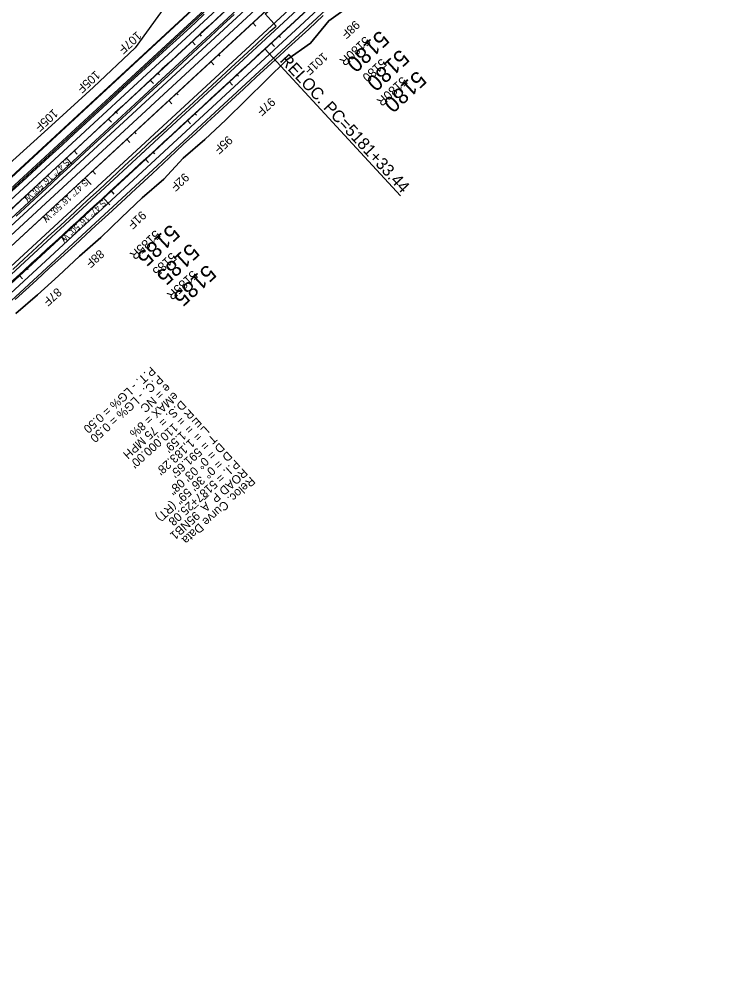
# Model space of a CAD drawing. Extents: x 2160876 to 2175990, y 601436 to 618246.
# Drawn here: x 2171138 to 2172369, y 611423 to 613107 of the extents above; entities that cross this region are included whole.
import ezdxf

# ---------------------------------------------------------------- set-up
doc = ezdxf.new("R2010")
doc.units = 0
for name, color, linetype in [('BNDY-ADJ', 7, 'Continuous'), ('BNDY-ADJ-TXT', 7, 'Continuous'), ('EX-UTIL-ELEC-TXT', 7, 'Continuous'), ('GN_Transparent 80', 7, 'Continuous'), ('RD_DTM_Major2', 7, 'Continuous'), ('RD_EX_BldgApp_Sign', 7, 'Continuous'), ('RD_EX_BldgApp_Steps', 7, 'Continuous'), ('RD_EX_DV_TX_Prop', 7, 'Continuous'), ('RD_EX_Fence_Gate', 7, 'Continuous'), ('RD_EX_Parking_Conc', 7, 'Continuous'), ('RD_EX_RW', 7, 'Continuous'), ('RD_HC_Cl', 7, 'Continuous'), ('RD_HC_Data_Tic', 7, 'Continuous'), ('RD_HC_TX_Sta50', 7, 'Continuous'), ('RD_TX_RoadID', 7, 'Continuous')]:
    doc.layers.add(name, color=color, linetype=linetype)

msp = doc.modelspace()

# ---------------------------------------------------------------- linework, layer by layer
at = {"layer": 'BNDY-ADJ'}
msp.add_line((2172239.9, 613739.9), (2163704.8, 605858.6), dxfattribs=at)
at = {"layer": 'BNDY-ADJ-TXT'}
for p, q in [((2172207.3, 613775.1), (2170395.2, 612101.8)), ((2172272.5, 613704.6), (2170460.3, 612031.3))]:
    msp.add_line(p, q, dxfattribs=at)
at = {"layer": 'EX-UTIL-ELEC-TXT'}
for p, q in [((2172179.3, 613805.5), (2170367.1, 612132.2)), ((2172180, 613804.8), (2170367.8, 612131.4)), ((2172199.2, 613784), (2170387, 612110.6)), ((2172207.3, 613775.1), (2170395.2, 612101.8)), ((2172215.5, 613766.3), (2170403.3, 612093)), ((2172264.3, 613713.4), (2170452.2, 612040.1)), ((2172272.5, 613704.6), (2170460.3, 612031.3)), ((2172261.1, 613677.8), (2170468.4, 612022.5))]:
    msp.add_line(p, q, dxfattribs=at)
at = {"layer": 'GN_Transparent 80'}
for p, q in [((2172189.5, 613794.5), (2170377.3, 612121.1)), ((2172191, 613792.8), (2170378.9, 612119.4))]:
    msp.add_line(p, q, dxfattribs=at)
at = {"layer": 'RD_DTM_Major2'}
for p, q in [((2171547.2, 613100.3), (2171552.7, 613094.4)), ((2171473.8, 613032.4), (2171479.2, 613026.6)), ((2171400.3, 612964.6), (2171405.7, 612958.7)), ((2171326.8, 612896.7), (2171332.2, 612890.9)), ((2171253.4, 612828.9), (2171264.2, 612817.2)), ((2171179.9, 612761.1), (2171185.3, 612755.2))]:
    msp.add_line(p, q, dxfattribs=at)
at = {"layer": 'RD_EX_BldgApp_Sign'}
msp.add_line((2170418.2, 612076.8), (2171614.4, 613181.4), dxfattribs=at)
at = {"layer": 'RD_EX_BldgApp_Steps'}
for p, q in [((2172672.7, 614139.6), (2163700.6, 605854.7)), ((2172327.8, 613755.9), (2171568.5, 613054.8)), ((2171454.4, 613080.2), (2171457.2, 613077.2)), ((2171593.1, 613077.4), (2171595.8, 613074.5)), ((2171487.2, 613044.8), (2171489.9, 613041.9)), ((2171806, 612797.6), (2171568.5, 613054.8)), ((2171381.1, 613012.2), (2171383.8, 613009.3)), ((2171519.6, 613009.6), (2171522.3, 613006.7)), ((2171413.7, 612977), (2171416.4, 612974)), ((2171307.8, 612944.2), (2171310.5, 612941.3)), ((2171446.1, 612941.8), (2171448.8, 612938.9)), ((2171340.2, 612909.1), (2171342.9, 612906.2)), ((2171234.5, 612876.2), (2171239.9, 612870.3)), ((2171372.5, 612874.2), (2171375.2, 612871.2)), ((2171266.8, 612841.3), (2171272.2, 612835.4)), ((2171161.3, 612808), (2171164, 612805.1)), ((2171298.8, 612806.5), (2171304.2, 612800.6)), ((2171193.3, 612773.5), (2171196, 612770.5)), ((2171225.1, 612739), (2171227.8, 612736)), ((2171151.3, 612671.5), (2171154, 612668.5))]:
    msp.add_line(p, q, dxfattribs=at)
for centre, start, end in [((2246150.8, 532330.8), 132.719474, 133.343763), ((2096943.5, 693870), 312.103138, 312.719474)]:
    msp.add_arc(centre, 110000, start, end, dxfattribs=at)
at = {"layer": 'RD_EX_Fence_Gate'}
for p, q in [((2171401.2, 613138.6), (2171341.1, 613056.4)), ((2171341.1, 613056.4), (2171268.6, 612987.6)), ((2171268.6, 612987.6), (2171194.8, 612920.4)), ((2171194.8, 612920.4), (2171120.6, 612853.6))]:
    msp.add_line(p, q, dxfattribs=at)
for points in [[(2171798.8, 613196.4), (2171758.2, 613166.6), (2171721.2, 613133), (2171680.3, 613103.5), (2171648.3, 613064.5), (2171606.8, 613035.7)], [(2171606.8, 613035.7), (2171571.1, 613000.7), (2171535.8, 612965.3), (2171500.1, 612930.2), (2171463.5, 612896.1), (2171425.7, 612863.4), (2171391.4, 612826.9), (2171353.8, 612793.8), (2171317.4, 612759.5), (2171281.4, 612724.8), (2171243.7, 612691.9), (2171207.3, 612657.7), (2171170.3, 612624.1), (2171132.3, 612591.5)]]:
    msp.add_lwpolyline(points, dxfattribs=at)
at = {"layer": 'RD_EX_RW'}
for p, q in [((2171401.2, 613138.6), (2171341.1, 613056.4)), ((2171341.1, 613056.4), (2171268.6, 612987.6)), ((2171268.6, 612987.6), (2171194.8, 612920.4)), ((2171194.8, 612920.4), (2171120.6, 612853.6))]:
    msp.add_line(p, q, dxfattribs=at)
for points in [[(2171588, 613094.5), (2171579.5, 613104.1), (2171569.3, 613115.9), (2171579, 613124), (2171613.5, 613148.4), (2171637.1, 613166.7), (2171663.6, 613187.6), (2171702.4, 613219.4), (2171737.4, 613247.4), (2171776.9, 613279.4), (2171788.2, 613288.5), (2171807.1, 613303), (2171822.2, 613314.9), (2171839.2, 613328.5), (2171850.3, 613338.1), (2171861.3, 613347.9)], [(2171606.8, 613035.7), (2171648.3, 613064.5), (2171680.3, 613103.5), (2171721.2, 613133), (2171758.2, 613166.6), (2171798.8, 613196.4)], [(2171119.8, 612800.3), (2171144.1, 612822.7), (2171168.6, 612845.4), (2171190.7, 612865.8), (2171214.2, 612887), (2171234, 612905.6), (2171255, 612924.6), (2171277.6, 612945.7), (2171299.7, 612966.2), (2171319, 612983.9), (2171339.7, 613003), (2171359.6, 613021.2), (2171375.7, 613035.8), (2171396.2, 613054.5), (2171412.9, 613069.7), (2171431.7, 613086.7), (2171446.6, 613100.4), (2171462.4, 613115.2)], [(2171514.9, 613114.6), (2171495, 613096.6), (2171472.6, 613075.8), (2171451.7, 613056.4), (2171423.8, 613030.5), (2171399.2, 613007.7), (2171373, 612983.6), (2171353, 612965.6), (2171333.4, 612947), (2171311.9, 612927.1), (2171288.4, 612905.5), (2171261.2, 612880.7), (2171234.4, 612855.6), (2171208.6, 612831.9), (2171185.5, 612810.5), (2171164.3, 612790.8), (2171148.4, 612775.7), (2171132.9, 612761.7)], [(2171670.6, 613113), (2171645.3, 613089.3), (2171609.9, 613057), (2171579.8, 613029.1), (2171553.3, 613005.1), (2171531.3, 612984.1), (2171510.2, 612964.8), (2171487.3, 612943.9), (2171468, 612926.1), (2171446.8, 612906.6), (2171425.5, 612887.2), (2171400.7, 612863.9), (2171371.3, 612835.8), (2171342.8, 612809.8), (2171316.7, 612785.6), (2171294.8, 612765.6), (2171272, 612744.9), (2171254.9, 612729.1), (2171235.6, 612711.2), (2171211.3, 612689)], [(2171127, 612668.6), (2171146.7, 612686.8), (2171169.2, 612707.7), (2171189.3, 612726.1), (2171210.5, 612745.6), (2171235.8, 612769), (2171257.9, 612789.6), (2171278.2, 612808.2), (2171299.3, 612827.8), (2171322.9, 612849.7), (2171350.1, 612875.1), (2171373, 612896.4), (2171394.8, 612915.9), (2171416.2, 612935.9), (2171435.8, 612953.7), (2171460.1, 612976), (2171484.4, 612998.9), (2171509.4, 613022), (2171531.2, 613042), (2171554.7, 613063.7), (2171577.9, 613085.5), (2171588, 613094.5)], [(2171132.3, 612591.5), (2171170.3, 612624.1), (2171207.3, 612657.7), (2171243.7, 612691.9), (2171281.4, 612724.8), (2171317.4, 612759.5), (2171353.8, 612793.8), (2171391.4, 612826.9), (2171425.7, 612863.4), (2171463.5, 612896.1), (2171500.1, 612930.2), (2171535.8, 612965.3), (2171571.1, 613000.7), (2171606.8, 613035.7)], [(2171211.3, 612689), (2171191.6, 612671.6), (2171168.6, 612649.9), (2171131.4, 612615.9)]]:
    msp.add_lwpolyline(points, dxfattribs=at)
at = {"layer": 'RD_HC_Cl'}
for p, q in [((2171441.2, 613067.7), (2171446.6, 613061.8)), ((2171579.8, 613065), (2171585.2, 613059.1)), ((2171367.7, 612999.9), (2171373.2, 612994)), ((2171506.3, 612997.2), (2171511.8, 612991.3)), ((2171294.3, 612932), (2171299.7, 612926.1)), ((2171432.9, 612929.3), (2171438.3, 612923.4)), ((2171220.8, 612864.2), (2171231.6, 612852.4)), ((2171359.4, 612861.5), (2171364.8, 612855.6)), ((2171147.3, 612796.3), (2171152.7, 612790.5)), ((2171285.9, 612793.6), (2171296.8, 612781.9)), ((2171212.4, 612725.8), (2171217.9, 612719.9)), ((2171139, 612658), (2171144.4, 612652.1))]:
    msp.add_line(p, q, dxfattribs=at)
at = {"layer": 'RD_TX_RoadID'}
for p, q in [((2172191, 613792.8), (2170378.9, 612119.4)), ((2172287.4, 613688.4), (2170475.2, 612015.1)), ((2171794.8, 613364.3), (2170410.1, 612085.6)), ((2171830.1, 613326.1), (2170445.4, 612047.4))]:
    msp.add_line(p, q, dxfattribs=at)

# ---------------------------------------------------------------- texts
at = {"layer": 'RD_EX_BldgApp_Steps'}
for s, height, rotation, p in [('5180', 28, 222.7195, (2171770, 613088.5)), ('RELOC. PC=5181+33.44', 21, 312.7195, (2171593.6, 613033.7)), ('5180', 28, 222.7195, (2171805.2, 613055.4)), ('5180', 28, 222.7195, (2171835.2, 613017.9)), ('5185', 28, 222.9263, (2171403.3, 612749.1)), ('5185', 28, 222.7195, (2171437.8, 612716.1)), ('5185', 28, 222.5285, (2171467.2, 612678.7)), ('P.T. - LG% = 0.50', 15, 222.1311, (2171369, 612499.7)), ('P.C. - LG% = 0.50', 15, 222.1311, (2171382.4, 612484.9)), ('eMAX = 8%', 15, 222.1311, (2171409.2, 612455.2)), ('e = NC', 15, 222.1311, (2171395.8, 612470)), ('D.S. =  75 MPH', 15, 222.1311, (2171422.6, 612440.4)), ("R = 110,000.00'", 15, 222.1311, (2171436.1, 612425.5)), ("E = 1.59'", 15, 222.1311, (2171449.5, 612410.7)), ("L = 1,183.28'", 15, 222.1311, (2171462.9, 612395.9)), ("T = 591.65'", 15, 222.1311, (2171476.3, 612381)), ('D = 0° 03\' 08"', 15, 222.1311, (2171489.7, 612366.2)), ('P.I. = 5187+25.08', 15, 222.1311, (2171516.6, 612336.5)), ('D', 15, 222.1311, (2171503.1, 612351.4)), ('    = 0° 36\' 59" (RT)', 15, 222.1311, (2171503.1, 612351.4)), ('ROAD P_A_95NB1', 15, 222.1311, (2171530, 612321.7)), ('Reloc. Curve Data', 15, 222.1311, (2171543.4, 612306.9))]:
    msp.add_text(s, height=height, rotation=rotation, dxfattribs=at).set_placement(p)
at = {"layer": 'RD_EX_DV_TX_Prop'}
for s, p in [('5180', (2171772.8, 613039)), ('5185', (2171405.1, 612699.5))]:
    msp.add_text(s, height=16, rotation=222.7195, dxfattribs=at).set_placement(p)
at = {"layer": 'RD_EX_Fence_Gate'}
for s, rotation, p in [('98F', 222.6747, (2171726.4, 613105.5)), ('107F', 222.4392, (2171344.3, 613086.4)), ('101F', 222.5962, (2171670.3, 613049.4)), ('105F', 222.3607, (2171271.9, 613017.7)), ('97F', 222.5177, (2171578.4, 612970.5)), ('105F', 222.2822, (2171198.1, 612950.5)), ('95F', 222.4392, (2171503.7, 612903.7)), ('92F', 222.3607, (2171427.6, 612838.6)), ('91F', 222.2822, (2171352.5, 612772.2)), ('88F', 222.2037, (2171278.9, 612704.4)), ('87F', 222.1253, (2171204.4, 612637.5))]:
    msp.add_text(s, height=15, rotation=rotation, dxfattribs=at).set_placement(p)
at = {"layer": 'RD_EX_Parking_Conc'}
msp.add_text('S 47° 16\' 50" W', height=10.8, rotation=222.7195, dxfattribs=at).set_placement((2171253.1, 612826.7))
at = {"layer": 'RD_HC_Data_Tic'}
for s, p in [('5180R', (2171744, 613077.8)), ('5180R', (2171809.1, 613007.3)), ('5185R', (2171376.7, 612738.6)), ('5185R', (2171441.8, 612668.1))]:
    msp.add_text(s, height=16, rotation=222.7195, dxfattribs=at).set_placement(p)
at = {"layer": 'RD_HC_TX_Sta50'}
for p in [(2171220.4, 612862.8), (2171284.4, 612791.3)]:
    msp.add_text('S 47° 16\' 50" W', height=10.8, rotation=222.7195, dxfattribs=at).set_placement(p)

doc.saveas('drawing.dxf')
